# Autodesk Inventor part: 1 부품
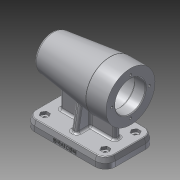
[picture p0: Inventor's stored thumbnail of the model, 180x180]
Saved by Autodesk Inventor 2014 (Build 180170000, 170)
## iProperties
Created: 2017-01
Part Number: 1 부품
Material: 알루미늄 6061
Document SubType Name: Modeling
Designer: owner
Density: 2.71 g/cm^3
Appearance: 알루미늄 - 평지
Mass: 795.212 g
Surface Area: 662.82 cm^2
Volume: 293.436 cm^3
Author: owner
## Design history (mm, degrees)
sketch "스케치1"
  geometry: L1 (-56, 0)-(56, 0); L2 (0, 0)-(0, 46.694); L3 (56, 0)-(56, 21); L4 (56, 21)-(56, 34); L5 (56, 34)-(28, 34); L6 (28, 34)-(-52.27, 24.144); L7 (56, 21)-(41, 21); L8 (41, 21)-(41, 24); L9 (41, 24)-(-13, 24); L10 (-13, 24)-(-13, 21); L11 (-13, 21)-(-25, 21); L12 (-25, 21)-(-25, 17.5); L13 (-25, 17.5)-(-43, 17.5); L14 (-43, 17.5)-(-43, 16); L15 (-43, 16)-(-47, 16); L16 (-47, 16)-(-47, 10.5); L17 (-47, 10.5)-(-50, 10.5); L18 (-50, 10.5)-(-50, 0); A1 r 80 centre (24, 0) between (-52.27, 24.144) and (-56, 0); 1 further point
  constraints: 36 end point, 10 parallel, 5 perpendicular, 2 point on circle, 2 point on line, 1 centre point, 1 coincident, 1 collinear, 1 horizontal, 1 horizontal alignment, 1 midpoint
  dimensions: "d0" = 112 distance of L1.start L1.end; "d1" = 68 diameter of L5 L1; "d2" = 7 deg angle of L5 L6; "d3" = 28 distance of L4.end L5.end; "d4" = 160 diameter of A1; "d5" = 48 diameter of L9 L1; "d6" = 42 diameter of L7 L1; "d7" = 15 distance of L3.end L7.end; "d8" = 54 distance of L8.end L9.end; "d9" = 12 distance of L10.end L11.end; "d10" = 18 distance of L12.end L13.end; "d12" = 3 distance of L16.end L17.end; "d13" = 4 distance of L14.end L15.end; "d14" = 35 diameter of L13 L1; "d15" = 32 diameter of L15 L1; "d16" = 21 diameter of L17 L1
revolve "회전1" sketch "스케치1" stored, may be unused: angle "d17" = 90 deg
node "작업 평면1"
sketch "스케치2"
  geometry: L1 (56, 35)-(-56, 35); L2 (-56, 35)-(-56, -35); L3 (-56, -35)-(56, -35); L4 (56, -35)-(56, 35); L5 (56, 35)-(-56, -35); L6 (-56, 35)-(56, -35); 1 further point
  constraints: 12 end point, 2 midpoint, 2 parallel, 1 horizontal, 1 perpendicular
  dimensions: "d22" = 112 distance of L2.end L3.end; "d23" = 70 distance of L1.end L2.end
extrude "돌출1" join sketch "스케치2" distance "d24" = 14; taper "d25" = 0 deg
sketch "스케치5"
  geometry: L1 (-52.27, -24.144)-(28, -34) reference; L2 (56, -74)-(-56, -74) reference; L3 (-56, -74)-(-56, -60) reference; L4 (56, -60)-(-56, -60) reference; L5 (56, -74)-(56, -60) reference; L6 (-38, -60)-(-38, -25.896); L7 (28, -34)-(56, -34) reference; L8 (38, -60)-(38, -34); L9 (38, -60)-(-38, -60); 1 further point
  constraints: 6 end point, 4 point on line, 1 collinear, 1 parallel, 1 perpendicular
  dimensions: "d31" = 18 horizontal distance of L2.end L6.start; "d33" = 18 distance from line of L2.start L8
feature "리브1" sketch "스케치5" dims "d34" = 1, "d35" = 8, "d36" = 0, "d37" = 0, "d38" = 1, "d39" = 1
sketch "스케치3"
  geometry: L1 (-74, -35)-(-74, 35) reference; L2 (-74, 35)-(-60, 35) reference; L3 (-60, -35)-(-60, 35) reference; L4 (-74, -35)-(-60, -35) reference; L5 (-60, 23)-(-18.376, 15.661); L6 (-60, -23)-(-18.376, -15.661); L7 (-60, 23)-(-60, -23); L8 (-33.764, -4)-(-25.585, -4) reference; L9 (-25.585, 4)-(-33.764, 4) reference; A1 r 24.144 centre (0, 0) between (-18.376, 15.661) and (-18.376, -15.661) reference; A2 r 34 centre (0, 0) between (-33.764, -4) and (-33.764, 4) reference; A3 r 24.144 centre (0, 0) between (-18.376, 15.661) and (-18.376, -15.661); A4 r 25.896 centre (0, 0) between (-25.585, 4) and (-25.585, -4) reference; 1 further point
  constraints: 6 end point, 4 point on circle, 2 point on line, 1 centre point, 1 coincident, 1 collinear, 1 concentric
  dimensions: "d26" = 100 deg angle of L3 L6; "d27" = 100 deg angle of L3 L5; "d28" = 12 vertical distance of L1.end L5.start; "d29" = 12 vertical distance of L1.start L6.start
extrude "돌출2" join sketch "스케치3" stored distance "d40" = 8; taper "d41" = 0 deg
sketch "스케치7"
  geometry: C1 r 34 at (0, 0) reference; 1 further point
  constraints: 1 vertical alignment
  dimensions: "d42" = 26 distance of C1.centre point (0, 26)
hole "구멍1" sketch "스케치7" at (0, 26) diameter "d43" = 3.242; stored, may be unused: countersink angle "d47" = 90 deg, drill point angle "d49" = 118 deg; dims "d44" = 8, "d45" = 4, "d46" = 2, "d48" = 11
fillet "모깎기1" dims "d53" = 0.3
fillet "모깎기2" dims "d54" = 3
fillet "모깎기3" dims "d55" = 3
chamfer "모따기2" distance "d56" = 1; stored, may be unused: second distance "d57" = 2, angle "d58" = 45 deg
fillet "모깎기4" dims "d59" = 3
fillet "모깎기5" dims "d72" = 14
chamfer "모따기7" distance "d73" = 7; stored, may be unused: second distance "d74" = 2, angle "d75" = 15 deg
sketch "스케치9"
  geometry: L1 (-39.113, -26)-(-44.887, -26); L2 (-44.887, -26)-(-47.774, -21); L3 (-47.774, -21)-(-44.887, -16); L4 (-44.887, -16)-(-39.113, -16); L5 (-39.113, -16)-(-36.226, -21); L6 (-36.226, -21)-(-39.113, -26); A1 r 12.124 centre (-42, -21) between (-54.124, -21) and (-42, -33.124) reference; 3 further points
  constraints: 12 end point, 1 coincident, 1 midpoint, 1 vertical alignment, 13 other
  dimensions: "d76" = 5 distance from line of L4 point (-42, -21)
extrude "돌출3" cut sketch "스케치9" distance "d78" = 4; taper "d79" = 0 deg
sketch "스케치10"
  geometry: C1 r 2.5 at (-42, -21); A1 r 12.124 centre (-42, -21) between (-54.124, -21) and (-42, -33.124) reference; 1 further point
  constraints: 1 centre point, 1 coincident
  dimensions: "d80" = 5 diameter of C1
extrude "돌출4" cut sketch "스케치10" stored distance "d81" = 4; taper "d82" = 0 deg
fillet "모깎기6" dims "d83" = 1
fillet "모깎기7" dims "d84" = 3
fillet "모깎기8" dims "d85" = 3
sketch "스케치12"
  geometry: L1 (0, 0)-(84, 0) reference; L2 (98, 0)-(98, 7) reference; 2 further points
  constraints: 1 other
  dimensions: "d86" = 56 distance from line of L2 point (42, 4); "d87" = 4 distance from line of L1 point (42, 4)
feature "엠보싱1" sketch "스케치12" dims "d0" = 112, "d1" = 68, "d2" = 7 deg, "d3" = 28, "d4" = 160, "d5" = 48, "d6" = 42, "d7" = 15, "d8" = 54, "d9" = 12, "d10" = 18, "d12" = 3, "d13" = 4, "d14" = 35, "d15" = 32, "d16" = 21, "d17" = 90 deg, "d88" = 0.5, "d89" = 0
node "솔리드1"
pattern_circular "원형 패턴1" dims angle "d51" = 360 deg
mirror "대칭1"
mirror "대칭2"
node "투영된 루프1"
node "투영된 루프2"
node "투영된 루프4"
other parameters: "d21" = -74
